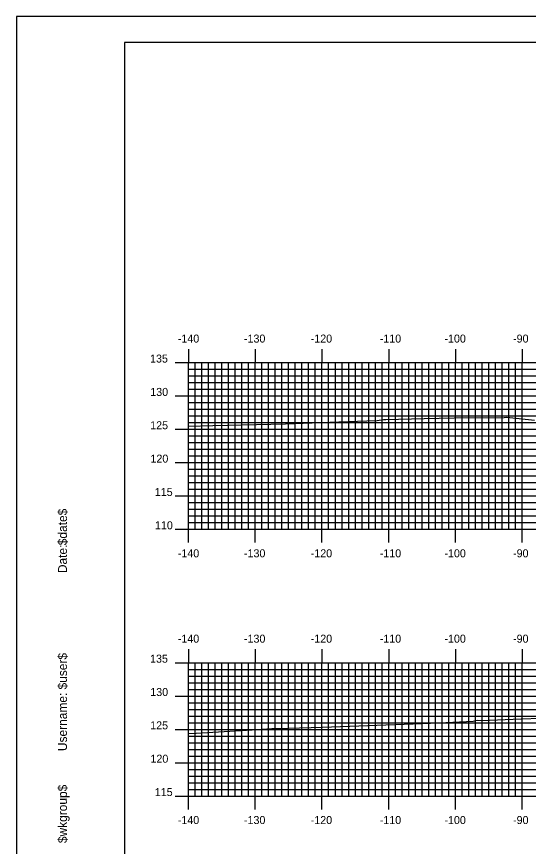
# Model space of a CAD drawing. Extents: x 842175 to 842518, y 363538 to 363758.
# Drawn here: x 842175.1 to 842251.8, y 363633.2 to 363757.6 of the extents above; entities that cross this region are included whole.
import ezdxf

# ---------------------------------------------------------------- set-up
doc = ezdxf.new("R2010")
doc.units = 0
for name, color, linetype in [('BORDER', 7, 'Continuous'), ('H_V ANNOTATION', 7, 'Continuous'), ('M_Roadway_Centerline', 7, 'Continuous'), ('MAJOR', 7, 'Continuous'), ('MINOR', 7, 'Continuous'), ('PLOT BOUNDARY', 7, 'Continuous'), ('S_Roadway_Centerline', 7, 'Continuous')]:
    doc.layers.add(name, color=color, linetype=linetype)

msp = doc.modelspace()

# ---------------------------------------------------------------- linework, layer by layer
at = {"layer": 'BORDER'}
msp.add_lwpolyline([(842191.29, 363543.72), (842511.29, 363543.72), (842511.29, 363753.72), (842191.29, 363753.72)], close=True, dxfattribs=at)
at = {"layer": 'MAJOR'}
for p, q in [((842200.89, 363707.73), (842200.89, 363705.72)), ((842210.89, 363707.73), (842210.89, 363705.72)), ((842220.89, 363707.73), (842220.89, 363705.72)), ((842230.89, 363707.73), (842230.89, 363705.72)), ((842240.89, 363707.73), (842240.89, 363705.72)), ((842250.89, 363707.73), (842250.89, 363705.72)), ((842198.88, 363705.72), (842200.89, 363705.72)), ((842200.89, 363705.72), (842480.89, 363705.72)), ((842200.89, 363680.72), (842200.89, 363705.72)), ((842200.89, 363680.72), (842200.89, 363705.72)), ((842200.89, 363705.72), (842480.89, 363705.72)), ((842210.89, 363680.72), (842210.89, 363705.72)), ((842220.89, 363680.72), (842220.89, 363705.72)), ((842230.89, 363680.72), (842230.89, 363705.72)), ((842240.89, 363680.72), (842240.89, 363705.72)), ((842250.89, 363680.72), (842250.89, 363705.72)), ((842198.88, 363700.72), (842200.89, 363700.72)), ((842200.89, 363700.72), (842480.89, 363700.72)), ((842198.88, 363695.72), (842200.89, 363695.72)), ((842200.89, 363695.72), (842480.89, 363695.72)), ((842198.88, 363690.72), (842200.89, 363690.72)), ((842200.89, 363690.72), (842480.89, 363690.72)), ((842198.88, 363685.72), (842200.89, 363685.72)), ((842200.89, 363685.72), (842480.89, 363685.72)), ((842198.88, 363680.72), (842200.89, 363680.72)), ((842200.89, 363680.72), (842480.89, 363680.72)), ((842200.89, 363680.72), (842480.89, 363680.72)), ((842200.89, 363678.72), (842200.89, 363680.72)), ((842210.89, 363678.72), (842210.89, 363680.72)), ((842220.89, 363678.72), (842220.89, 363680.72)), ((842230.89, 363678.72), (842230.89, 363680.72)), ((842240.89, 363678.72), (842240.89, 363680.72)), ((842250.89, 363678.72), (842250.89, 363680.72)), ((842200.89, 363662.73), (842200.89, 363660.72)), ((842210.89, 363662.73), (842210.89, 363660.72)), ((842220.89, 363662.73), (842220.89, 363660.72)), ((842230.89, 363662.73), (842230.89, 363660.72)), ((842240.89, 363662.73), (842240.89, 363660.72)), ((842250.89, 363662.73), (842250.89, 363660.72)), ((842198.88, 363660.72), (842200.89, 363660.72)), ((842200.89, 363660.72), (842480.89, 363660.72)), ((842200.89, 363640.72), (842200.89, 363660.72)), ((842200.89, 363640.72), (842200.89, 363660.72)), ((842200.89, 363660.72), (842480.89, 363660.72)), ((842210.89, 363640.72), (842210.89, 363660.72)), ((842220.89, 363640.72), (842220.89, 363660.72)), ((842230.89, 363640.72), (842230.89, 363660.72)), ((842240.89, 363640.72), (842240.89, 363660.72)), ((842250.89, 363640.72), (842250.89, 363660.72)), ((842198.88, 363655.72), (842200.89, 363655.72)), ((842200.89, 363655.72), (842480.89, 363655.72)), ((842198.88, 363650.72), (842200.89, 363650.72)), ((842200.89, 363650.72), (842480.89, 363650.72)), ((842198.88, 363645.72), (842200.89, 363645.72)), ((842200.89, 363645.72), (842480.89, 363645.72)), ((842198.88, 363640.72), (842200.89, 363640.72)), ((842200.89, 363640.72), (842480.89, 363640.72)), ((842200.89, 363640.72), (842480.89, 363640.72)), ((842200.89, 363638.72), (842200.89, 363640.72)), ((842210.89, 363638.72), (842210.89, 363640.72)), ((842220.89, 363638.72), (842220.89, 363640.72)), ((842230.89, 363638.72), (842230.89, 363640.72)), ((842240.89, 363638.72), (842240.89, 363640.72)), ((842250.89, 363638.72), (842250.89, 363640.72))]:
    msp.add_line(p, q, dxfattribs=at)
at = {"layer": 'MINOR'}
for p, q in [((842201.89, 363680.72), (842201.89, 363705.72)), ((842202.89, 363680.72), (842202.89, 363705.72)), ((842203.89, 363680.72), (842203.89, 363705.72)), ((842204.89, 363680.72), (842204.89, 363705.72)), ((842205.89, 363680.72), (842205.89, 363705.72)), ((842206.89, 363680.72), (842206.89, 363705.72)), ((842207.89, 363680.72), (842207.89, 363705.72)), ((842208.89, 363680.72), (842208.89, 363705.72)), ((842209.89, 363680.72), (842209.89, 363705.72)), ((842211.89, 363680.72), (842211.89, 363705.72)), ((842212.89, 363680.72), (842212.89, 363705.72)), ((842213.89, 363680.72), (842213.89, 363705.72)), ((842214.89, 363680.72), (842214.89, 363705.72)), ((842215.89, 363680.72), (842215.89, 363705.72)), ((842216.89, 363680.72), (842216.89, 363705.72)), ((842217.89, 363680.72), (842217.89, 363705.72)), ((842218.89, 363680.72), (842218.89, 363705.72)), ((842219.89, 363680.72), (842219.89, 363705.72)), ((842221.89, 363680.72), (842221.89, 363705.72)), ((842222.89, 363680.72), (842222.89, 363705.72)), ((842223.89, 363680.72), (842223.89, 363705.72)), ((842224.89, 363680.72), (842224.89, 363705.72)), ((842225.89, 363680.72), (842225.89, 363705.72)), ((842226.89, 363680.72), (842226.89, 363705.72)), ((842227.89, 363680.72), (842227.89, 363705.72)), ((842228.89, 363680.72), (842228.89, 363705.72)), ((842229.89, 363680.72), (842229.89, 363705.72)), ((842231.89, 363680.72), (842231.89, 363705.72)), ((842232.89, 363680.72), (842232.89, 363705.72)), ((842233.89, 363680.72), (842233.89, 363705.72)), ((842234.89, 363680.72), (842234.89, 363705.72)), ((842235.89, 363680.72), (842235.89, 363705.72)), ((842236.89, 363680.72), (842236.89, 363705.72)), ((842237.89, 363680.72), (842237.89, 363705.72)), ((842238.89, 363680.72), (842238.89, 363705.72)), ((842239.89, 363680.72), (842239.89, 363705.72)), ((842241.89, 363680.72), (842241.89, 363705.72)), ((842242.89, 363680.72), (842242.89, 363705.72)), ((842243.89, 363680.72), (842243.89, 363705.72)), ((842244.89, 363680.72), (842244.89, 363705.72)), ((842245.89, 363680.72), (842245.89, 363705.72)), ((842246.89, 363680.72), (842246.89, 363705.72)), ((842247.89, 363680.72), (842247.89, 363705.72)), ((842248.89, 363680.72), (842248.89, 363705.72)), ((842249.89, 363680.72), (842249.89, 363705.72)), ((842200.89, 363704.72), (842480.89, 363704.72)), ((842200.89, 363704.72), (842202.89, 363704.72)), ((842200.89, 363703.72), (842480.89, 363703.72)), ((842200.89, 363703.72), (842202.89, 363703.72)), ((842200.89, 363702.72), (842480.89, 363702.72)), ((842200.89, 363702.72), (842202.89, 363702.72)), ((842200.89, 363701.72), (842480.89, 363701.72)), ((842200.89, 363701.72), (842202.89, 363701.72)), ((842200.89, 363699.72), (842480.89, 363699.72)), ((842200.89, 363699.72), (842202.89, 363699.72)), ((842200.89, 363698.72), (842480.89, 363698.72)), ((842200.89, 363698.72), (842202.89, 363698.72)), ((842200.89, 363697.72), (842480.89, 363697.72)), ((842200.89, 363697.72), (842202.89, 363697.72)), ((842200.89, 363696.72), (842480.89, 363696.72)), ((842200.89, 363696.72), (842202.89, 363696.72)), ((842200.89, 363694.72), (842480.89, 363694.72)), ((842200.89, 363694.72), (842202.89, 363694.72)), ((842200.89, 363693.72), (842480.89, 363693.72)), ((842200.89, 363693.72), (842202.89, 363693.72)), ((842200.89, 363692.72), (842480.89, 363692.72)), ((842200.89, 363692.72), (842202.89, 363692.72)), ((842200.89, 363691.72), (842480.89, 363691.72)), ((842200.89, 363691.72), (842202.89, 363691.72)), ((842200.89, 363689.72), (842480.89, 363689.72)), ((842200.89, 363689.72), (842202.89, 363689.72)), ((842200.89, 363688.72), (842480.89, 363688.72)), ((842200.89, 363688.72), (842202.89, 363688.72)), ((842200.89, 363687.72), (842480.89, 363687.72)), ((842200.89, 363687.72), (842202.89, 363687.72)), ((842200.89, 363686.72), (842480.89, 363686.72)), ((842200.89, 363686.72), (842202.89, 363686.72)), ((842200.89, 363684.72), (842480.89, 363684.72)), ((842200.89, 363684.72), (842202.89, 363684.72)), ((842200.89, 363683.72), (842480.89, 363683.72)), ((842200.89, 363683.72), (842202.89, 363683.72)), ((842200.89, 363682.72), (842480.89, 363682.72)), ((842200.89, 363682.72), (842202.89, 363682.72)), ((842200.89, 363681.72), (842480.89, 363681.72)), ((842200.89, 363681.72), (842202.89, 363681.72)), ((842201.89, 363640.72), (842201.89, 363660.72)), ((842202.89, 363640.72), (842202.89, 363660.72)), ((842203.89, 363640.72), (842203.89, 363660.72)), ((842204.89, 363640.72), (842204.89, 363660.72)), ((842205.89, 363640.72), (842205.89, 363660.72)), ((842206.89, 363640.72), (842206.89, 363660.72)), ((842207.89, 363640.72), (842207.89, 363660.72)), ((842208.89, 363640.72), (842208.89, 363660.72)), ((842209.89, 363640.72), (842209.89, 363660.72)), ((842211.89, 363640.72), (842211.89, 363660.72)), ((842212.89, 363640.72), (842212.89, 363660.72)), ((842213.89, 363640.72), (842213.89, 363660.72)), ((842214.89, 363640.72), (842214.89, 363660.72)), ((842215.89, 363640.72), (842215.89, 363660.72)), ((842216.89, 363640.72), (842216.89, 363660.72)), ((842217.89, 363640.72), (842217.89, 363660.72)), ((842218.89, 363640.72), (842218.89, 363660.72)), ((842219.89, 363640.72), (842219.89, 363660.72)), ((842221.89, 363640.72), (842221.89, 363660.72)), ((842222.89, 363640.72), (842222.89, 363660.72)), ((842223.89, 363640.72), (842223.89, 363660.72)), ((842224.89, 363640.72), (842224.89, 363660.72)), ((842225.89, 363640.72), (842225.89, 363660.72)), ((842226.89, 363640.72), (842226.89, 363660.72)), ((842227.89, 363640.72), (842227.89, 363660.72)), ((842228.89, 363640.72), (842228.89, 363660.72)), ((842229.89, 363640.72), (842229.89, 363660.72)), ((842231.89, 363640.72), (842231.89, 363660.72)), ((842232.89, 363640.72), (842232.89, 363660.72)), ((842233.89, 363640.72), (842233.89, 363660.72)), ((842234.89, 363640.72), (842234.89, 363660.72)), ((842235.89, 363640.72), (842235.89, 363660.72)), ((842236.89, 363640.72), (842236.89, 363660.72)), ((842237.89, 363640.72), (842237.89, 363660.72)), ((842238.89, 363640.72), (842238.89, 363660.72)), ((842239.89, 363640.72), (842239.89, 363660.72)), ((842241.89, 363640.72), (842241.89, 363660.72)), ((842242.89, 363640.72), (842242.89, 363660.72)), ((842243.89, 363640.72), (842243.89, 363660.72)), ((842244.89, 363640.72), (842244.89, 363660.72)), ((842245.89, 363640.72), (842245.89, 363660.72)), ((842246.89, 363640.72), (842246.89, 363660.72)), ((842247.89, 363640.72), (842247.89, 363660.72)), ((842248.89, 363640.72), (842248.89, 363660.72)), ((842249.89, 363640.72), (842249.89, 363660.72)), ((842200.89, 363659.72), (842480.89, 363659.72)), ((842200.89, 363659.72), (842202.89, 363659.72)), ((842200.89, 363658.72), (842480.89, 363658.72)), ((842200.89, 363658.72), (842202.89, 363658.72)), ((842200.89, 363657.72), (842480.89, 363657.72)), ((842200.89, 363657.72), (842202.89, 363657.72)), ((842200.89, 363656.72), (842480.89, 363656.72)), ((842200.89, 363656.72), (842202.89, 363656.72)), ((842200.89, 363654.72), (842480.89, 363654.72)), ((842200.89, 363654.72), (842202.89, 363654.72)), ((842200.89, 363653.72), (842480.89, 363653.72)), ((842200.89, 363653.72), (842202.89, 363653.72)), ((842200.89, 363652.72), (842480.89, 363652.72)), ((842200.89, 363652.72), (842202.89, 363652.72)), ((842200.89, 363651.72), (842480.89, 363651.72)), ((842200.89, 363651.72), (842202.89, 363651.72)), ((842200.89, 363649.72), (842480.89, 363649.72)), ((842200.89, 363649.72), (842202.89, 363649.72)), ((842200.89, 363648.72), (842480.89, 363648.72)), ((842200.89, 363648.72), (842202.89, 363648.72)), ((842200.89, 363647.72), (842480.89, 363647.72)), ((842200.89, 363647.72), (842202.89, 363647.72)), ((842200.89, 363646.72), (842480.89, 363646.72)), ((842200.89, 363646.72), (842202.89, 363646.72)), ((842200.89, 363644.72), (842480.89, 363644.72)), ((842200.89, 363644.72), (842202.89, 363644.72)), ((842200.89, 363643.72), (842480.89, 363643.72)), ((842200.89, 363643.72), (842202.89, 363643.72)), ((842200.89, 363642.72), (842480.89, 363642.72)), ((842200.89, 363642.72), (842202.89, 363642.72)), ((842200.89, 363641.72), (842480.89, 363641.72)), ((842200.89, 363641.72), (842202.89, 363641.72))]:
    msp.add_line(p, q, dxfattribs=at)
at = {"layer": 'PLOT BOUNDARY'}
msp.add_lwpolyline([(842175.1, 363537.6), (842515.1, 363537.6), (842515.1, 363757.6), (842175.1, 363757.6)], close=True, dxfattribs=at)
at = {"layer": 'S_Roadway_Centerline'}
for points in [[(842200.89, 363696.2), (842204.52, 363696.3), (842215.44, 363696.53), (842223.4, 363696.81), (842227.59, 363696.96), (842229.16, 363697.02), (842230.11, 363697.17), (842230.47, 363697.17), (842236.21, 363697.35), (842240.69, 363697.44), (842248.23, 363697.46), (842248.59, 363697.51), (842252.77, 363697.07)], [(842200.89, 363650.1), (842202.01, 363650.16), (842210.44, 363650.66), (842213.38, 363650.85), (842214.64, 363650.84), (842215.84, 363650.89), (842220.98, 363651.07), (842234.58, 363651.55), (842238.44, 363651.72), (842243.54, 363651.97), (842244.15, 363652.09), (842244.82, 363652.07), (842250.74, 363652.32), (842253.68, 363652.38)]]:
    msp.add_lwpolyline(points, dxfattribs=at)

# ---------------------------------------------------------------- texts
at = {"layer": 'BORDER'}
for s, p in [('$date$', (842182.65, 363678.33)), ('Date:', (842182.65, 363674.15)), ('$user$', (842182.65, 363656.7)), ('Username:', (842182.65, 363647.46)), ('$wkgroup$', (842182.65, 363633.66))]:
    msp.add_text(s, height=1.339, rotation=90, dxfattribs=at).set_placement(p)
at = {"layer": 'H_V ANNOTATION'}
for s, p in [('-140', (842199.27, 363708.72)), ('-130', (842209.19, 363708.72)), ('-120', (842219.2, 363708.72)), ('-110', (842229.55, 363708.72)), ('-100', (842239.25, 363708.72)), ('-90', (842249.54, 363708.72)), ('135', (842195.11, 363705.72)), ('130', (842195.14, 363700.72)), ('125', (842195.13, 363695.72)), ('120', (842195.17, 363690.72)), ('115', (842195.82, 363685.72)), ('110', (842195.85, 363680.72)), ('-140', (842199.27, 363676.52)), ('-130', (842209.19, 363676.52)), ('-120', (842219.2, 363676.52)), ('-110', (842229.55, 363676.52)), ('-100', (842239.25, 363676.52)), ('-90', (842249.54, 363676.52)), ('-140', (842199.27, 363663.72)), ('-130', (842209.19, 363663.72)), ('-120', (842219.2, 363663.72)), ('-110', (842229.55, 363663.72)), ('-100', (842239.25, 363663.72)), ('-90', (842249.54, 363663.72)), ('135', (842195.11, 363660.72)), ('130', (842195.14, 363655.72)), ('125', (842195.13, 363650.72)), ('120', (842195.17, 363645.72)), ('115', (842195.82, 363640.72)), ('-140', (842199.27, 363636.52)), ('-130', (842209.19, 363636.52)), ('-120', (842219.2, 363636.52)), ('-110', (842229.55, 363636.52)), ('-100', (842239.25, 363636.52)), ('-90', (842249.54, 363636.52))]:
    msp.add_text(s, height=1.2, dxfattribs=at).set_placement(p)
at = {"layer": 'M_Roadway_Centerline'}
for s, p in [('C', (842244.14, 363652.09)), ('L', (842244.15, 363652.08)), ('C', (842213.37, 363650.85)), ('L', (842213.38, 363650.84))]:
    msp.add_text(s, height=0.0146, dxfattribs=at).set_placement(p)
at = {"layer": 'MAJOR'}
for p in [(842200.88, 363680.72), (842200.88, 363640.72)]:
    msp.add_text('-', height=0.012, dxfattribs=at).set_placement(p)

doc.saveas('drawing.dxf')
